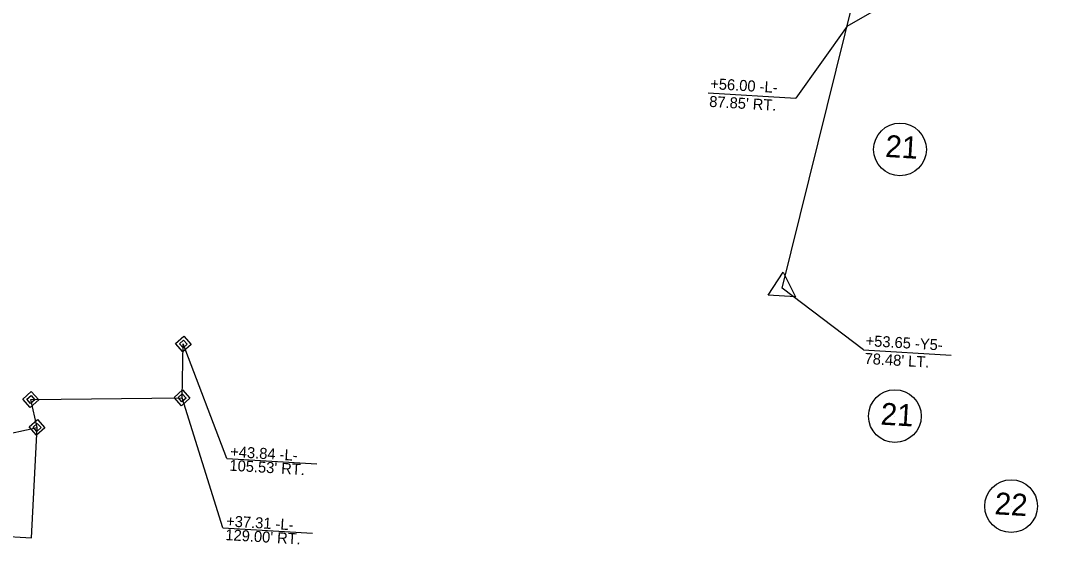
# Model space of a CAD drawing. Extents: x 2010883 to 2014849, y 442000 to 447413.
# Drawn here: x 2013529.9 to 2013997.9, y 444773.5 to 445011.9 of the extents above; entities that cross this region are included whole.
import ezdxf

# ---------------------------------------------------------------- set-up
doc = ezdxf.new("R2010")
doc.units = 0
for name, color, linetype in [('Prop Easement Construction', 7, 'Continuous'), ('Prop Easement Construction Station Offsets', 7, 'Continuous'), ('Prop Easement Permanent Utility', 7, 'Continuous'), ('Prop Easement Permanent Utility Station Offsets', 7, 'Continuous'), ('Prop Parcel Number CELL', 7, 'Continuous'), ('Prop Parcel Number Text', 7, 'Continuous'), ('Prop ROW Marker CELL', 7, 'Continuous'), ('Prop ROW Permanent Easement CELL', 7, 'Continuous'), ('Prop ROW RW Lines', 7, 'Continuous'), ('Prop ROW Station Offsets', 7, 'Continuous')]:
    doc.layers.add(name, color=color, linetype=linetype)

msp = doc.modelspace()

# ---------------------------------------------------------------- linework, layer by layer
at = {"layer": 'Prop Easement Construction'}
msp.add_line((2013906.21, 445009.36), (2013997.94, 445062.16), dxfattribs=at)
at = {"layer": 'Prop Easement Construction Station Offsets'}
for p in [(2013906.21, 445009.36), (2013843, 444978.98)]:
    msp.add_line(p, (2013882.93, 444976.63), dxfattribs=at)
at = {"layer": 'Prop Easement Permanent Utility'}
for p, q in [((2013603.43, 444840.23), (2013604, 444864.75)), ((2013534.54, 444839.48), (2013603.43, 444840.23)), ((2013537.4, 444826.79), (2013534.54, 444839.48)), ((2013517.04, 444822.36), (2013537.4, 444826.79))]:
    msp.add_line(p, q, dxfattribs=at)
at = {"layer": 'Prop Easement Permanent Utility Station Offsets'}
for p, q in [((2013623.83, 444812.62), (2013604, 444864.75)), ((2013621.97, 444781.04), (2013603.43, 444840.23)), ((2013534.91, 444776.56), (2013537.4, 444826.79)), ((2013623.83, 444812.62), (2013664.72, 444810.21)), ((2013621.97, 444781.04), (2013662.86, 444778.63)), ((2013494.02, 444778.97), (2013534.91, 444776.56))]:
    msp.add_line(p, q, dxfattribs=at)
at = {"layer": 'Prop Parcel Number CELL'}
for p, q in [((2013930.34, 444953.26), (2013930.34, 444953.26)), ((2013928.01, 444831.94), (2013928.01, 444831.94)), ((2013980.94, 444790.96), (2013980.94, 444790.96))]:
    msp.add_line(p, q, dxfattribs=at)
for centre in [(2013930.34, 444953.26), (2013928.01, 444831.94), (2013980.94, 444790.96)]:
    msp.add_circle(centre, 12, dxfattribs=at)
at = {"layer": 'Prop ROW Marker CELL'}
for p, q in [((2013876.69, 444890.19), (2013876.69, 444890.19)), ((2013604, 444864.75), (2013604, 444864.75)), ((2013603.43, 444840.23), (2013603.43, 444840.23)), ((2013534.54, 444839.48), (2013534.54, 444839.48)), ((2013537.4, 444826.79), (2013537.4, 444826.79))]:
    msp.add_line(p, q, dxfattribs=at)
msp.add_lwpolyline([(2013870.24, 444886.96), (2013877.11, 444897.38), (2013882.71, 444886.23)], close=True, dxfattribs=at)
at = {"layer": 'Prop ROW Permanent Easement CELL'}
for points in [[(2013604.21, 444868.35), (2013607.59, 444864.54), (2013603.79, 444861.16), (2013600.41, 444864.96)], [(2013604.11, 444866.55), (2013605.8, 444864.65), (2013603.89, 444862.96), (2013602.2, 444864.86)], [(2013534.76, 444843.07), (2013538.14, 444839.26), (2013534.33, 444835.88), (2013530.95, 444839.69)], [(2013534.65, 444841.27), (2013536.34, 444839.37), (2013534.44, 444837.68), (2013532.75, 444839.58)], [(2013603.65, 444843.82), (2013607.03, 444840.02), (2013603.22, 444836.64), (2013599.84, 444840.44)], [(2013603.54, 444842.03), (2013605.23, 444840.12), (2013603.33, 444838.43), (2013601.64, 444840.33)], [(2013537.61, 444830.39), (2013541, 444826.58), (2013537.19, 444823.2), (2013533.81, 444827.01)], [(2013537.51, 444828.59), (2013539.2, 444826.69), (2013537.3, 444825), (2013535.6, 444826.9)]]:
    msp.add_lwpolyline(points, close=True, dxfattribs=at)
at = {"layer": 'Prop ROW RW Lines'}
msp.add_line((2013876.69, 444890.19), (2013918.9, 445060.55), dxfattribs=at)
at = {"layer": 'Prop ROW Station Offsets'}
for q in [(2013876.69, 444890.19), (2013953.68, 444859.69)]:
    msp.add_line((2013913.75, 444862.05), q, dxfattribs=at)

# ---------------------------------------------------------------- texts
at = {"layer": 'Prop Easement Construction Station Offsets'}
for s, p in [('+56.00 -L-', (2013843.83, 444980.76)), ("87.85' RT.", (2013843.35, 444972.65))]:
    msp.add_text(s, height=5, rotation=356.6264, dxfattribs=at).set_placement(p)
at = {"layer": 'Prop Easement Permanent Utility Station Offsets'}
for s, p in [('+43.84 -L-', (2013625.26, 444813.35)), ("105.53' RT.", (2013624.89, 444807.11)), ('+37.31 -L-', (2013623.4, 444781.77)), ("129.00' RT.", (2013623.03, 444775.53))]:
    msp.add_text(s, height=5, rotation=356.6264, dxfattribs=at).set_placement(p)
at = {"layer": 'Prop Parcel Number Text'}
for s, p in [('21', (2013923.45, 444949.87)), ('21', (2013921.35, 444828.08)), ('22', (2013973.26, 444787.29))]:
    msp.add_text(s, height=10, rotation=356.6264, dxfattribs=at).set_placement(p)
at = {"layer": 'Prop ROW Station Offsets'}
for s, p in [('+53.65 -Y5-', (2013914.58, 444863.83)), ("78.48' LT.", (2013914.1, 444855.72))]:
    msp.add_text(s, height=5, rotation=356.6264, dxfattribs=at).set_placement(p)

doc.saveas('drawing.dxf')
